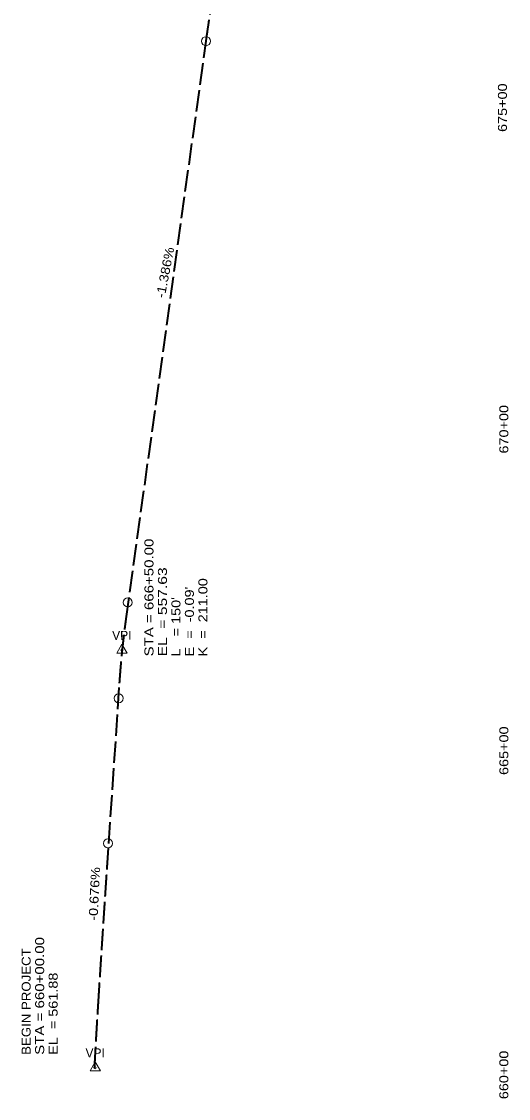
# Model space of a CAD drawing. Extents: x 2363427 to 2368559, y 6957299 to 6980140.
# Drawn here: x 2366091 to 2366849, y 6966805 to 6968482 of the extents above; entities that cross this region are included whole.
import ezdxf
from ezdxf.enums import TextEntityAlignment as Align

# ---------------------------------------------------------------- set-up
doc = ezdxf.new("R2010")
doc.units = 0
doc.header["$LTSCALE"] = 5.6
doc.linetypes.add('LONG_DASHED', pattern=[7.5, 6, -1.5])
doc.layers.add('44', color=7, linetype='Continuous', lineweight=13)
doc.layers.add('61', color=7, linetype='Continuous', lineweight=25)

msp = doc.modelspace()

# ---------------------------------------------------------------- linework, layer by layer
at = {"layer": '44', "linetype": 'LONG_DASHED', "lineweight": 35}
for p, q in [((2366253.544, 6967551.988), (2366378.033, 6968452.021)), ((2366226.416, 6967201.981), (2366243.26, 6967451.985))]:
    msp.add_line(p, q, dxfattribs=at)
at = {"layer": '44'}
for p, q in [((2366246.78, 6967512.457), (2366238.742, 6967498.441)), ((2366246.78, 6967512.457), (2366254.903, 6967498.491)), ((2366238.742, 6967498.441), (2366254.903, 6967498.491)), ((2366205.278, 6966862.173), (2366197.24, 6966848.157)), ((2366205.278, 6966862.173), (2366213.401, 6966848.207)), ((2366197.24, 6966848.157), (2366213.401, 6966848.207))]:
    msp.add_line(p, q, dxfattribs=at)
for centre, radius in [((2366377.733, 6968451.828), 7), ((2366256.022, 6967577.626), 7), ((2366246.799, 6967503.126), 1.5), ((2366241.689, 6967428.271), 7), ((2366225.145, 6967202.36), 7), ((2366205.296, 6966852.843), 1.5)]:
    msp.add_circle(centre, radius, dxfattribs=at)
at = {"layer": '44', "linetype": 'LONG_DASHED', "lineweight": 35}
for points in [[(2366378.033, 6968452.021), (2366379.437, 6968462.021), (2366380.886, 6968472.021), (2366382.378, 6968482.022), (2366383.914, 6968492.022), (2366385.493, 6968502.023), (2366387.115, 6968512.023), (2366388.782, 6968522.023), (2366390.492, 6968532.024), (2366392.245, 6968542.024), (2366394.042, 6968552.025), (2366395.882, 6968562.025), (2366397.767, 6968572.026), (2366399.694, 6968582.026), (2366401.665, 6968592.027), (2366403.68, 6968602.027), (2366405.738, 6968612.028), (2366407.839, 6968622.028), (2366409.985, 6968632.029), (2366412.173, 6968642.03), (2366414.406, 6968652.03), (2366416.682, 6968662.031), (2366419.001, 6968672.031), (2366421.364, 6968682.032), (2366423.771, 6968692.033), (2366426.22, 6968702.033), (2366428.714, 6968712.034), (2366431.251, 6968722.035), (2366433.833, 6968732.035), (2366436.456, 6968742.036), (2366439.124, 6968752.037), (2366441.836, 6968762.037), (2366444.59, 6968772.038), (2366447.388, 6968782.039), (2366450.231, 6968792.04), (2366453.116, 6968802.04), (2366456.046, 6968812.041), (2366459.018, 6968822.042), (2366462.034, 6968832.043), (2366465.094, 6968842.043), (2366468.197, 6968852.044), (2366471.343, 6968862.045), (2366474.534, 6968872.046), (2366477.768, 6968882.047), (2366481.046, 6968892.048), (2366484.366, 6968902.049), (2366487.73, 6968912.049), (2366491.139, 6968922.05), (2366494.59, 6968932.051), (2366498.085, 6968942.052), (2366501.624, 6968952.053)], [(2366243.26, 6967451.985), (2366243.395, 6967453.985), (2366243.534, 6967455.985), (2366243.676, 6967457.985), (2366243.82, 6967459.985), (2366243.969, 6967461.985), (2366244.118, 6967463.985), (2366244.272, 6967465.985), (2366244.428, 6967467.985), (2366244.587, 6967469.986), (2366244.748, 6967471.986), (2366244.913, 6967473.986), (2366245.08, 6967475.986), (2366245.251, 6967477.986), (2366245.424, 6967479.986), (2366245.6, 6967481.986), (2366245.778, 6967483.986), (2366245.96, 6967485.986), (2366246.144, 6967487.986), (2366246.332, 6967489.986), (2366246.522, 6967491.986), (2366246.714, 6967493.986), (2366246.91, 6967495.986), (2366247.109, 6967497.986), (2366247.311, 6967499.986), (2366247.514, 6967501.986), (2366247.722, 6967503.986), (2366247.931, 6967505.986), (2366248.145, 6967507.986), (2366248.36, 6967509.987), (2366248.579, 6967511.987), (2366248.8, 6967513.987), (2366249.024, 6967515.987), (2366249.251, 6967517.987), (2366249.481, 6967519.987), (2366249.713, 6967521.987), (2366249.949, 6967523.987), (2366250.187, 6967525.987), (2366250.429, 6967527.987), (2366250.673, 6967529.987), (2366250.92, 6967531.987), (2366251.169, 6967533.987), (2366251.421, 6967535.987), (2366251.677, 6967537.987), (2366251.935, 6967539.987), (2366252.196, 6967541.988), (2366252.46, 6967543.988), (2366252.727, 6967545.988), (2366252.996, 6967547.988), (2366253.269, 6967549.988), (2366253.544, 6967551.988)], [(2366210.106, 6966951.976), (2366210.421, 6966956.977), (2366210.737, 6966961.977), (2366211.054, 6966966.977), (2366211.372, 6966971.977), (2366211.688, 6966976.977), (2366212.007, 6966981.977), (2366212.325, 6966986.977), (2366212.643, 6966991.977), (2366212.963, 6966996.977), (2366213.283, 6967001.977), (2366213.602, 6967006.977), (2366213.923, 6967011.977), (2366214.244, 6967016.978), (2366214.565, 6967021.978), (2366214.887, 6967026.978), (2366215.209, 6967031.978), (2366215.531, 6967036.978), (2366215.854, 6967041.978), (2366216.178, 6967046.978), (2366216.502, 6967051.978), (2366216.826, 6967056.978), (2366217.151, 6967061.978), (2366217.476, 6967066.978), (2366217.801, 6967071.978), (2366218.127, 6967076.979), (2366218.454, 6967081.979), (2366218.78, 6967086.979), (2366219.108, 6967091.979), (2366219.436, 6967096.979), (2366219.763, 6967101.979), (2366220.092, 6967106.979), (2366220.421, 6967111.979), (2366220.75, 6967116.979), (2366221.08, 6967121.979), (2366221.411, 6967126.979), (2366221.742, 6967131.98), (2366222.072, 6967136.98), (2366222.404, 6967141.98), (2366222.736, 6967146.98), (2366223.068, 6967151.98), (2366223.401, 6967156.98), (2366223.735, 6967161.98), (2366224.068, 6967166.98), (2366224.402, 6967171.98), (2366224.737, 6967176.98), (2366225.071, 6967181.98), (2366225.407, 6967186.98), (2366225.743, 6967191.981), (2366226.079, 6967196.981), (2366226.416, 6967201.981)], [(2366204.329, 6966851.975), (2366204.433, 6966853.975), (2366204.539, 6966855.975), (2366204.645, 6966857.975), (2366204.752, 6966859.975), (2366204.858, 6966861.975), (2366204.966, 6966863.975), (2366205.073, 6966865.975), (2366205.181, 6966867.975), (2366205.289, 6966869.975), (2366205.399, 6966871.975), (2366205.508, 6966873.975), (2366205.618, 6966875.975), (2366205.728, 6966877.975), (2366205.839, 6966879.975), (2366205.95, 6966881.975), (2366206.062, 6966883.975), (2366206.173, 6966885.975), (2366206.286, 6966887.975), (2366206.398, 6966889.975), (2366206.512, 6966891.976), (2366206.625, 6966893.976), (2366206.739, 6966895.976), (2366206.854, 6966897.976), (2366206.968, 6966899.976), (2366207.084, 6966901.976), (2366207.199, 6966903.976), (2366207.316, 6966905.976), (2366207.432, 6966907.976), (2366207.55, 6966909.976), (2366207.667, 6966911.976), (2366207.785, 6966913.976), (2366207.903, 6966915.976), (2366208.022, 6966917.976), (2366208.141, 6966919.976), (2366208.261, 6966921.976), (2366208.38, 6966923.976), (2366208.501, 6966925.976), (2366208.622, 6966927.976), (2366208.744, 6966929.976), (2366208.865, 6966931.976), (2366208.987, 6966933.976), (2366209.11, 6966935.976), (2366209.232, 6966937.976), (2366209.356, 6966939.976), (2366209.48, 6966941.976), (2366209.604, 6966943.976), (2366209.729, 6966945.976), (2366209.854, 6966947.976), (2366209.979, 6966949.976), (2366210.106, 6966951.976)]]:
    msp.add_spline(points, degree=3, dxfattribs=at)

# ---------------------------------------------------------------- texts
at = {"layer": '44', "width": 1.2}
for s, p in [('675+00', (2366846.451, 6968348.255)), ('670+00', (2366848.607, 6967847.34)), ('665+00', (2366848.607, 6967346.668)), ('660+00', (2366848.607, 6966841.641))]:
    msp.add_text(s, height=14, rotation=90, dxfattribs=at).set_placement(p, align=Align.CENTER)
at = {"layer": '44'}
for s, rotation, width, p in [('-1.386%', 79.108, 1.15, (2366313.337, 6968050.787)), ('-0.676%', 87.108, 1.2, (2366208.852, 6967081.488))]:
    msp.add_text(s, height=14, rotation=rotation, dxfattribs=dict(at, width=width)).set_placement(p)
for p in [(2366246.773, 6967519.327), (2366205.27, 6966869.043)]:
    msp.add_text('VPI', height=14, rotation=0.175, dxfattribs=at).set_placement(p, align=Align.CENTER)
at = {"layer": '61'}
for s, width, p in [('STA = 666+50.00', 1.25, (2366295.977, 6967493.555)), ('EL  = 557.63', 1.3, (2366316.977, 6967493.555)), ('K  =  211.00', 1.2, (2366379.979, 6967493.555)), ("E  =  -0.09'", 1.2, (2366358.978, 6967493.555)), ("L   = 150'", 1.2, (2366337.978, 6967493.555)), ('STA = 660+00.00', 1.25, (2366125.764, 6966872.966)), ('BEGIN PROJECT', 1.1, (2366104.764, 6966872.966)), ('EL  = 561.88', 1.2, (2366146.765, 6966872.966))]:
    msp.add_text(s, height=14, rotation=90, dxfattribs=dict(at, width=width)).set_placement(p)

doc.saveas('drawing.dxf')
